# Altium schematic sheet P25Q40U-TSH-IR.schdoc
size 127 x 101 mm
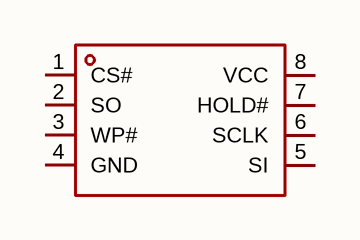
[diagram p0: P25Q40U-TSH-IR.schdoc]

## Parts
U?  p25q40u-tsh-ir  [TSSOP-8_L4.4-W3.0-P0.65-LS6.4-BL]  (value not drawn)

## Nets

Not connected (* = marked no-connect by the designer): U? 1(CS#) 2(SO) 3(WP#) 4(GND) 5(SI) 6(SCLK) 7(HOLD#) 8(VCC)

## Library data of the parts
U? = p25q40u-tsh-ir: 接口类型:SPI;存储容量:4Mbit;时钟频率(fc):104MHz;; Manufacturer: PUYA(普冉); AddInBom: yes; ModelId: 85577802f9634e7e85ffa2fd25a37b6f; ModelName: TSSOP-8_L4.4-W3.0-P0.65-LS6.4-BL-2; ModelTransform: 118.11,251.968,0,0,0,0,0,0,0; Interface: SPI; Memory Size: 4Mbit; Clock Frequency: 104MHz; Voltage - Supply: 1.65V~3.6V; Standby Supply Current: 9uA; Program / Erase Cycles: 100000次; Page Programming Time (Tpp): 2ms; Data Retention - TDR (Year): 20年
